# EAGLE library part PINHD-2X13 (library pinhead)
PIN HEADER
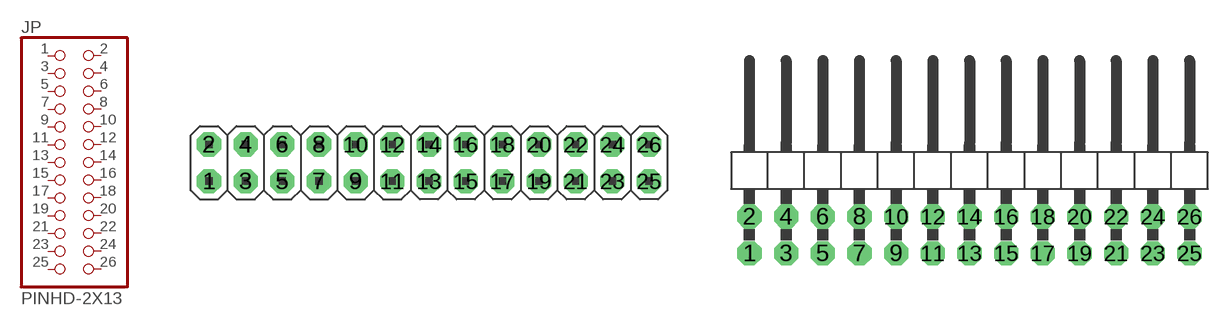
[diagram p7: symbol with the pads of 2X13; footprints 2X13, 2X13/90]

Designator prefix JP

## PINHD-2X13  [2X13]
1  1  pas
2  2  pas
3  3  pas
4  4  pas
5  5  pas
6  6  pas
7  7  pas
8  8  pas
9  9  pas
10  10  pas
11  11  pas
12  12  pas
13  13  pas
14  14  pas
15  15  pas
16  16  pas
17  17  pas
18  18  pas
19  19  pas
20  20  pas
21  21  pas
22  22  pas
23  23  pas
24  24  pas
25  25  pas
26  26  pas

## PINHD-2X13/90  [2X13/90]
Pads as for 2X13

## Footprint 2X13 (pad centres in mm)
PIN HEADER
drill 1.016 pad 1.67 octagon: 1 -15.24,-1.27; 2 -15.24,1.27; 3 -12.7,-1.27; 4 -12.7,1.27; 5 -10.16,-1.27; 6 -10.16,1.27; 7 -7.62,-1.27; 8 -7.62,1.27; 9 -5.08,-1.27; 10 -5.08,1.27; 11 -2.54,-1.27; 12 -2.54,1.27; 13 0,-1.27; 14 0,1.27; 15 2.54,-1.27; 16 2.54,1.27; 17 5.08,-1.27; 18 5.08,1.27; 19 7.62,-1.27; 20 7.62,1.27; 21 10.16,-1.27; 22 10.16,1.27; 23 12.7,-1.27; 24 12.7,1.27; 25 15.24,-1.27; 26 15.24,1.27

## Footprint 2X13/90 (pad centres in mm)
PIN HEADER
drill 1.016 pad 1.67 octagon: 1 -15.24,-6.35; 2 -15.24,-3.81; 3 -12.7,-6.35; 4 -12.7,-3.81; 5 -10.16,-6.35; 6 -10.16,-3.81; 7 -7.62,-6.35; 8 -7.62,-3.81; 9 -5.08,-6.35; 10 -5.08,-3.81; 11 -2.54,-6.35; 12 -2.54,-3.81; 13 0,-6.35; 14 0,-3.81; 15 2.54,-6.35; 16 2.54,-3.81; 17 5.08,-6.35; 18 5.08,-3.81; 19 7.62,-6.35; 20 7.62,-3.81; 21 10.16,-6.35; 22 10.16,-3.81; 23 12.7,-6.35; 24 12.7,-3.81; 25 15.24,-6.35; 26 15.24,-3.81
